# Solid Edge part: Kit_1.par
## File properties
Author: bmolnar
Last saved by: bmolnar
Revision: 76
Sűrűség: 0,000 kg/m^3
Pontosság: 0,990
Username: bmolnar
Dokumentum tartalom típus: 0
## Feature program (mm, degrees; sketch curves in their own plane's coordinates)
base feature "unnamed BaseFeature 1"
sketch for "unnamed Cutout 1" plane through (0, 0.0012, 83.3) normal (0, 0, -1) x-axis (-1, 0, 0)
  circle centre (0, -0.0012) radius 8
extrude "unnamed Cutout 1" cut through along -normal
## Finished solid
Body 1: solid body, 48 faces, 65 edges, 51 vertices, 1 internal void.
  Faces by surface: cone 16, cylinder 16, plane 12, torus 4
  Edges by curve: circle 51, line 14
Bounding box of the edges (mm; curved faces can reach further): 55.000 x 54.575 x 12.300, from (-27.5, -25.9, 83.3) to (27.5, 28.675, 95.6).
Cylindrical faces by radius (mm): R1.25 x2, R2.5 x4, R8 x1, R8.27 x1, R8.85 x1, R9 x1, R10.16 x1, R10.25 x1, R17 x1, R23.975 x1, R25.9 x1, R27.5 x1
Conical faces (half-angle, radius in mm at the cone's reference point): 3 deg R10.205 x1, 7 deg R9.5925 x1, 14 deg R8.135 x1, 14 deg R8.4811 x1, 17 deg R8.135 x1, 23 deg R8.829 x1, 42.5 deg R8.1233 x1, 45 deg R9.1 x2, 45 deg R16.5 x1, 45 deg R25.8 x2, 84 deg R76.3675 x2, 85 deg R9.9463 x1, 87 deg R8.1765 x1
Toroidal faces (ring radius, tube radius in mm): R8.8057 r0.2025 x1, R9.2522 r0.2925 x1, R9.96 r0.2 x1, R17.8 r0.8 x1
Planar faces by outward normal: +z 7, -z 3, oblique 2
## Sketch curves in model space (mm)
circle centre (0, 0, 83.3) radius 8
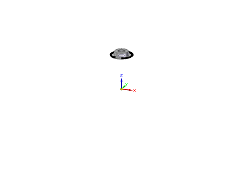
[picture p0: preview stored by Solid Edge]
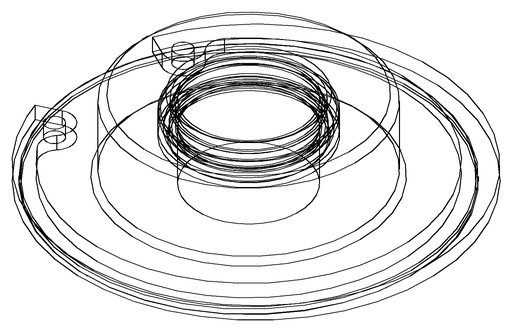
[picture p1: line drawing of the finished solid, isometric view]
